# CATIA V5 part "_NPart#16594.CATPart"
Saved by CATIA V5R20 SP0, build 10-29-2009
Part number: 1BOLAØ2,3
Revision: ANY
Definition: UNKNOWN
Nomenclature: 1BOLAØ2,3
Source: Unknown
Bounding box of the stored display mesh (mm): x -1.19 to 1.19, y -1.19 to 1.19, z -1.19 to 1.19
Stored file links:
  C:\Users\Utente\Desktop\IO LAVORO\3D X SITO CF\CUMSA\3D files AE\AE 062430\_NPart#16594.CATPart
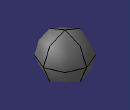
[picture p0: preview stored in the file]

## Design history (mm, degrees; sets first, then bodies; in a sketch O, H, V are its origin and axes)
Body1 "Revolución1" (main body)
  Solid1: solid without history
